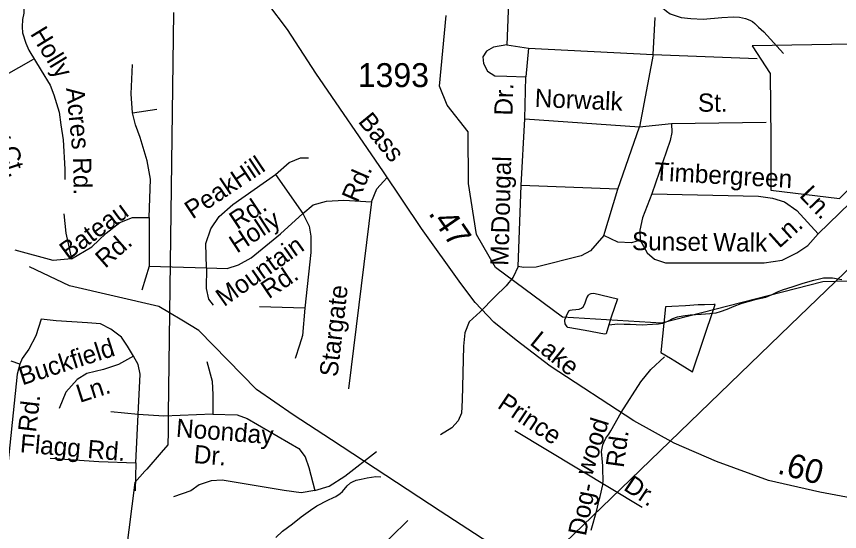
# Model space of a CAD drawing. Extents: x 2001466 to 2224147, y 644118 to 847247.
# Drawn here: x 2051357 to 2055654, y 689808 to 692499 of the extents above; entities that cross this region are included whole.
import ezdxf

# ---------------------------------------------------------------- set-up
doc = ezdxf.new("R2010")
doc.units = 0
for name, color, linetype in [('Exist Boundary Political City Limit New Hole', 7, 'Continuous'), ('Exist Hydrographic Creek Single Shore', 7, 'Continuous'), ('Exist Hydrographic Misc Water Feature', 7, 'Continuous'), ('Exist Road Non-System Type 51', 7, 'Continuous'), ('Exist Road Non-System Type 51 Label', 7, 'Continuous'), ('Exist Road Secondary Mileage Hundredths English Label', 7, 'Continuous'), ('Exist Road Secondary Type 51 Attributed', 7, 'Continuous'), ('Exist Road Secondary Type 51 Label', 7, 'Continuous'), ('Exist Road Secondary Type 51 Number Label', 7, 'Continuous'), ('Exist Utilities Electrical Transmission Line', 7, 'Continuous'), ('Map Preparation Boundary City Limit Buffer Line', 7, 'Continuous')]:
    doc.layers.add(name, color=color, linetype=linetype)

msp = doc.modelspace()

# ---------------------------------------------------------------- linework, layer by layer
at = {"layer": 'Exist Boundary Political City Limit New Hole'}
for points in [[(2055291, 692200.8), (2055294.9, 691856.9), (2055294.9, 691591.2), (2055654.6, 691548.2), (2056307.6, 692204.6), (2056307.6, 692259.4), (2055717.2, 692353.1), (2055197.1, 692345.3), (2055291, 692200.8)], [(2054794.5, 690699.9), (2054886.6, 690642.8), (2055000, 690978.4), (2055005.2, 690993.9), (2055000, 690993.8), (2054998.1, 690993.8), (2054949, 690992.5), (2054915.2, 690991.7), (2054849.2, 690987.6), (2054779, 690983.3), (2054744.5, 690981.7), (2054720.1, 690743.2), (2054771.5, 690713.6), (2054794.5, 690699.9)]]:
    msp.add_lwpolyline(points, dxfattribs=at)
at = {"layer": 'Exist Hydrographic Creek Single Shore'}
for p, q in [((2052219.8, 690911.5), (2052156.3, 690949.7)), ((2053568.5, 689915.2), (2053002, 690286.3)), ((2053822.9, 689748.5), (2053568.5, 689915.2))]:
    msp.add_line(p, q, dxfattribs=at)
for points in [[(2052156.3, 690949.7), (2052099.9, 690983.5), (2051634.1, 691091.4), (2051425.1, 691190.8)], [(2053002, 690286.3), (2052801, 690418.1), (2052609.1, 690550), (2052309.1, 690857.9), (2052219.8, 690911.5)]]:
    msp.add_lwpolyline(points, dxfattribs=at)
at = {"layer": 'Exist Hydrographic Misc Water Feature'}
for points in [[(2055633.4, 691114.4), (2055565.9, 691113.1), (2054725, 690897.3), (2054208.1, 690927.5), (2053858.1, 691187.3), (2053758, 691359.9), (2053716, 691626.5), (2053715.1, 691895.6), (2053606, 692035.6), (2053565, 692134.9), (2053600.5, 692503.7)], [(2054449.4, 690888.6), (2054495.6, 690892.5), (2054529.8, 690890.6), (2054561.6, 690890.6), (2054623.5, 690887), (2054677.2, 690891), (2054709.4, 690893), (2054731.4, 690897), (2054757.4, 690907.2), (2054783.5, 690921.1), (2054807.4, 690929.2), (2054835.1, 690935.2), (2054873.3, 690939.6), (2054931.3, 690943.3), (2054977, 690947.7), (2055009.2, 690949.8), (2055033.2, 690957.9), (2055067.5, 690969.7), (2055103.3, 690985.8), (2055140.9, 690999.9), (2055177, 691009.9), (2055221, 691021.9), (2055269, 691032), (2055302.9, 691046.3), (2055330.7, 691060.4), (2055357, 691070.2), (2055411.1, 691088.4), (2055458.9, 691104.3), (2055488.6, 691112.7), (2055519, 691120.7), (2055548.7, 691128.8), (2055570.7, 691132.7), (2055617, 691132.6), (2055666.6, 691125.1)], [(2057830.9, 689897.6), (2057633.9, 690060.5), (2057576.1, 690170), (2057426, 690333.8), (2057167, 690509.7), (2057033.1, 690650.2), (2056866, 690916), (2056774.9, 690999.9), (2056241, 691125.6), (2055633.4, 691114.4)], [(2054229.2, 690934.2), (2054241.3, 690960.3), (2054247.4, 690964.3), (2054257.5, 690966.4), (2054277.4, 690968.2), (2054295.2, 690970.4), (2054307.3, 690974.2), (2054315.5, 690982.3), (2054323.3, 690998.2), (2054335, 691028.4), (2054343.4, 691042.2), (2054349, 691048.2), (2054356.9, 691052.3), (2054371.1, 691052.6), (2054495.2, 691022.8), (2054461.3, 690928.6), (2054449.4, 690888.6)], [(2054449.4, 690888.6), (2054435.5, 690840.4), (2054427.5, 690838.4), (2054325.4, 690858.3), (2054235.4, 690874), (2054231.5, 690878.2), (2054221.4, 690892.3), (2054219.4, 690908.1), (2054219.6, 690914.1), (2054227.4, 690930), (2054229.2, 690934.2)], [(2052711.6, 689777.5), (2052745.9, 689809.6), (2052797.7, 689847.6), (2052843.5, 689885.7), (2052891.6, 689919.7), (2052925.7, 689941.8), (2052981.7, 689971.8), (2053011.6, 689986), (2053023.3, 689991.9), (2053047.3, 690006.1), (2053059.4, 690018), (2053083.2, 690046), (2053101.2, 690062.4), (2053111.1, 690068.2), (2053131.1, 690076.5), (2053157.2, 690082.3), (2053187.1, 690088.3), (2053233.1, 690096.3), (2053259.1, 690094.4)]]:
    msp.add_lwpolyline(points, dxfattribs=at)
at = {"layer": 'Exist Road Non-System Type 51'}
for points in [[(2054650.5, 693715.8), (2054676.9, 692673.7), (2054685.8, 692584.6), (2054706.6, 692557.9), (2054738.6, 692537.1), (2054750.3, 692526.9), (2054770.1, 692512.5), (2054785.9, 692506.2), (2054805.8, 692499.8), (2054827.7, 692493.3), (2054877.6, 692488.3), (2054941.5, 692485), (2055039.7, 692493), (2055099.7, 692495.8), (2055131.7, 692495.1), (2055163.6, 692488.5), (2055185.4, 692480), (2055199.2, 692471.8), (2055211, 692461.5), (2055230.6, 692443.1), (2055258.1, 692418.6), (2055361.8, 692304.4)], [(2053647, 692679.6), (2053911.4, 692667.7), (2053925.7, 692653.4), (2053928, 692617.7), (2053916.1, 692350.5)], [(2051397.4, 692612.1), (2051394.8, 692516.6), (2051387.9, 692482.2), (2051386.2, 692444.4), (2051387.9, 692413.5), (2051405.1, 692358.5), (2051420.4, 692323.1)], [(2054681.7, 692300.4), (2054691.2, 692493.5)], [(2053916.1, 692350.5), (2053847, 692338.6), (2053811.3, 692317.1), (2053792.3, 692288.5), (2053794.6, 692252.8), (2053816.1, 692212.2), (2053854.2, 692188.4), (2053916.1, 692186), (2054016.2, 692183.6)], [(2053916.1, 692350.5), (2054030.5, 692333.8)], [(2051420.4, 692323.1), (2051485.7, 692216.2), (2051533.2, 692139.6), (2051551, 692088.5), (2051579.5, 691998.7), (2051588.1, 691931.7), (2051600.1, 691854.7), (2051608.7, 691700.1), (2051608.7, 691646.9)], [(2054030.5, 692333.8), (2054016.2, 692183.6)], [(2054030.5, 692333.8), (2054681.7, 692300.4)], [(2054681.7, 692300.4), (2054610.2, 691921.5)], [(2054681.7, 692300.4), (2055223.8, 692279)], [(2055542, 691363.3), (2056491.9, 692284.2), (2056549, 692327.1)], [(2051163, 692169), (2051291.8, 692187.9), (2051446.3, 692275.5)], [(2051961.8, 691995.1), (2051955.5, 692095.2), (2051961.8, 692248.5)], [(2054011.4, 691963.9), (2054016.2, 692183.6)], [(2051961.8, 691995.1), (2052089.9, 692013.9)], [(2052049.3, 691447.8), (2052055.6, 691648), (2052039.9, 691744.9), (2052002.4, 691866.9), (2051977.4, 691932.6), (2051961.8, 691995.1)], [(2053992.3, 691615.9), (2054011.4, 691963.9)], [(2054011.4, 691963.9), (2054610.2, 691921.5)], [(2054496.3, 691596.8), (2054610.2, 691921.5)], [(2054610.2, 691921.5), (2054776, 691938.6)], [(2054776, 691938.6), (2054778.4, 691893.3), (2054768.8, 691850.4), (2054673.6, 691571.6)], [(2054776, 691938.6), (2055271.4, 691945.8)], [(2052708.8, 691673), (2052780.7, 691735.5), (2052840.1, 691760.5), (2052880.7, 691760.5)], [(2052349.4, 691185.1), (2052346.2, 691313.3), (2052371.3, 691388.4), (2052415, 691454), (2052486.9, 691516.6), (2052708.8, 691673)], [(2052708.8, 691673), (2052852.6, 691469.7)], [(2053209.5, 691530), (2053237.7, 691598.8), (2053272.1, 691636.4), (2053292.9, 691657.2)], [(2053975.7, 691191.7), (2053992.3, 691615.9)], [(2054496.3, 691596.8), (2053992.3, 691615.9)], [(2054422.5, 691353.7), (2054496.3, 691596.8)], [(2054673.6, 691571.6), (2054625, 691446.7), (2054610.7, 691382.3), (2054613.1, 691329.9)], [(2054673.6, 691571.6), (2055230.9, 691559.7), (2055304.8, 691550.1), (2055366.7, 691531.1), (2055431, 691485.8), (2055542, 691363.3)], [(2052852.6, 691469.7), (2052906.4, 691514.4), (2052975.1, 691533.2), (2053065.8, 691539.4), (2053209.5, 691530)], [(2053209.5, 691530), (2053090.8, 690552.9)], [(2051603.6, 691468), (2051614.8, 691367.1), (2051644.8, 691232.6), (2051548.6, 691224), (2051350.7, 691278)], [(2051644.8, 691232.6), (2051749.3, 691294.5), (2051824.3, 691366.5), (2051896.2, 691422.8), (2051961.8, 691447.8), (2052049.3, 691447.8)], [(2052049.3, 691447.8), (2052049.3, 691194.4)], [(2052349.4, 691185.1), (2052456.3, 691181.6), (2052515.7, 691200.4), (2052581.3, 691237.9), (2052734.4, 691363), (2052852.6, 691469.7)], [(2052852.6, 691469.7), (2052884.5, 691403.7), (2052893.9, 691350.5), (2052893.9, 691266.1), (2052862.6, 690975.2)], [(2054613.1, 691329.9), (2054650.2, 691264.1), (2054688.3, 691230.8), (2054745.5, 691211.7), (2055260, 691211.7), (2055355.2, 691226), (2055431.5, 691264.1), (2055488.6, 691302.3), (2055542, 691363.3)], [(2054422.5, 691353.7), (2054354.4, 691275.1), (2054304.4, 691248.9), (2054070.9, 691189.3), (2054004.3, 691186.9), (2053975.7, 691191.7)], [(2054613.1, 691329.9), (2054567.8, 691315.6), (2054496.3, 691320.4), (2054422.5, 691353.7)], [(2052049.3, 691194.4), (2052011.8, 691069.3)], [(2052049.3, 691194.4), (2052349.4, 691185.1)], [(2052349.4, 691185.1), (2052346.9, 691078.4), (2052359.4, 691022.1), (2052384.4, 690990.8)], [(2053975.7, 691191.7), (2053949.5, 691136.6), (2053913.7, 691091.3), (2053854.2, 691034.1), (2053778, 690955.5)], [(2052862.6, 690975.2), (2052625.1, 690981.4)], [(2052862.6, 690975.2), (2052850.1, 690831.3), (2052834.5, 690781.3), (2052812.6, 690712.5)], [(2053778, 690955.5), (2053719.9, 690902.8), (2053698.4, 690845.6), (2053691.3, 690776.5), (2053684.1, 690495.2), (2053679.4, 690426.1), (2053662.7, 690385.6), (2053629.3, 690349.8), (2053569.8, 690314.1)], [(2051486.1, 690917.6), (2051457.9, 690830.1), (2051420.4, 690761.3), (2051386.1, 690711.2), (2051373.6, 690683.1)], [(2051967.4, 690723.7), (2051936.2, 690776.9), (2051904.9, 690823.8), (2051848.6, 690864.5), (2051795.5, 690892.6), (2051726.7, 690898.9), (2051564.2, 690908.3), (2051486.1, 690917.6)], [(2051967.4, 690723.7), (2051889.3, 690679.9), (2051811.1, 690654.9), (2051723.6, 690633), (2051673.6, 690601.7), (2051614.2, 690536.1), (2051579.8, 690451.6)], [(2051992.4, 690420.3), (2052001.8, 690629.9), (2051992.4, 690679.9), (2051967.4, 690723.7)], [(2054514.1, 690429.7), (2054616.9, 690589.4), (2054669.3, 690653.7), (2054740.7, 690720.5)], [(2051373.6, 690683.1), (2051361.1, 690629.9), (2051301.7, 690057.5)], [(2051373.6, 690683.1), (2051329.8, 690698.7)], [(2052350, 690696.8), (2052378.1, 690593.6), (2052381.3, 690521.7), (2052381.3, 690421.6)], [(2051992.4, 690420.3), (2051848.6, 690432.8)], [(2051979.9, 690167), (2051992.4, 690420.3)], [(2052381.3, 690421.6), (2052126.8, 690411), (2051992.4, 690420.3)], [(2052381.3, 690421.6), (2052508.2, 690417.2), (2052561.3, 690398.4), (2052830.1, 690242.1), (2052864.5, 690198.3), (2052883.2, 690142), (2052914.5, 690023.1)], [(2054356.9, 689815), (2054386.6, 689920.3), (2054397.6, 689966), (2054404.1, 689991.9), (2054417.3, 690051.6), (2054419.9, 690077.6), (2054418.9, 690129.6), (2054417.4, 690151.6), (2054415.7, 690169.7), (2054410.9, 690225.8), (2054417.6, 690261.6), (2054423.9, 690273.5), (2054434.3, 690295.3), (2054448.8, 690317), (2054459.1, 690334.8), (2054514.1, 690429.7)], [(2053959.5, 690336.7), (2054624, 689936.3)], [(2052914.5, 690023.1), (2052989.5, 690045), (2053070.8, 690098.2), (2053236.4, 690226.4)], [(2051533, 690192), (2051786.1, 690173.2), (2051979.9, 690167)], [(2051979.9, 690167), (2051976.8, 690020)], [(2052914.5, 690023.1), (2052842.6, 690010.6), (2052755.1, 690023.1), (2052430, 690076.3), (2052373.8, 690073.2), (2052311.2, 690051.3), (2052267.5, 690020), (2052176.8, 689988.7)], [(2053222.4, 689692.3), (2053399.6, 689865.3)]]:
    msp.add_lwpolyline(points, dxfattribs=at)
at = {"layer": 'Exist Road Secondary Type 51 Attributed'}
msp.add_lwpolyline([(2057671.9, 689435.8), (2057551.9, 689500.6), (2057342.1, 689604.8), (2057192.2, 689663.2), (2056983.9, 689724), (2056542.1, 689823.5), (2055933, 689942.7), (2055551.2, 690013.7), (2055282.9, 690075.3), (2055011.5, 690174), (2054790.6, 690270.3), (2054579.2, 690387.2), (2054143.7, 690672.2), (2053965.4, 690808), (2053848.6, 690901.1), (2053750.8, 691005.3), (2053676.6, 691103.2), (2053471.5, 691391.4), (2053272.7, 691686.7), (2052919.2, 692202.2), (2052770.9, 692431.2), (2052668.3, 692566.2)], dxfattribs=at)
at = {"layer": 'Exist Utilities Electrical Transmission Line'}
for p, q in [((2052176.5, 692518.6), (2052156.3, 690949.7)), ((2055396.8, 690886), (2055633.4, 691114.4)), ((2052156.3, 690949.7), (2052149.4, 690419.2)), ((2054768.2, 690279.2), (2055396.8, 690886)), ((2052149.4, 690419.2), (2052148.3, 690329.2)), ((2054461.1, 689982.7), (2054768.2, 690279.2)), ((2054312.9, 689839.6), (2054461.1, 689982.7)), ((2054058.5, 689594.1), (2054312.9, 689839.6))]:
    msp.add_line(p, q, dxfattribs=at)
for points in [[(2055633.4, 691114.4), (2056033.6, 691500.7), (2057399.4, 692809)], [(2052148.3, 690329.2), (2052147.4, 690260.3), (2052113, 690220.7)], [(2052113, 690220.7), (2052037.6, 690134.1), (2052027.5, 690123)], [(2052027.5, 690123), (2051973.8, 690064), (2051927.6, 689693.9)]]:
    msp.add_lwpolyline(points, dxfattribs=at)
at = {"layer": 'Map Preparation Boundary City Limit Buffer Line'}
for points in [[(2055291, 692200.8), (2055294.9, 691856.9), (2055294.9, 691591.2), (2055654.6, 691548.2), (2056307.6, 692204.6), (2056307.6, 692259.4), (2055717.2, 692353.1), (2055197.1, 692345.3), (2055291, 692200.8)], [(2054794.5, 690699.9), (2054886.6, 690642.8), (2055000, 690978.4), (2055005.2, 690993.9), (2055000, 690993.8), (2054998.1, 690993.8), (2054949, 690992.5), (2054915.2, 690991.7), (2054849.2, 690987.6), (2054779, 690983.3), (2054744.5, 690981.7), (2054720.1, 690743.2), (2054771.5, 690713.6), (2054794.5, 690699.9)]]:
    msp.add_lwpolyline(points, dxfattribs=at)

# ---------------------------------------------------------------- texts
at = {"layer": 'Exist Road Non-System Type 51 Label'}
for s, rotation, p in [('Holly', 301.418, (2051426, 692408.3)), ('Holiday Ct.', 287.9206, (2051129.2, 692241.4)), ('Dr.', 88.4479, (2053946, 691980)), ('Acres', 275.6158, (2051615.5, 692123.9)), ('Norwalk', 357.5094, (2054061.2, 692026.5)), ('St.', 359.744, (2054914.2, 692001.2)), ('Rd.', 270.798, (2051652.4, 691762.6)), ('PeakHill', 33.7235, (2052275.6, 691437.7)), ('McDougal', 88.4478, (2053924.8, 691195.4)), ('Rd.', 66.6986, (2053138.3, 691521.5)), ('Timbergreen', 356.816, (2054685, 691642.3)), ('Ln.', 313.5435, (2055440.1, 691560)), ('Rd.', 33.7235, (2052508.7, 691382.7)), ('Bateau', 36.3151, (2051626, 691223.5)), ('Holly', 33.2103, (2052507.5, 691259.2)), ('Ln.', 41.9273, (2055338.7, 691284.3)), ('Rd.', 41.2682, (2051820, 691179.8)), ('Sunset', 359.2879, (2054569.9, 691278.3)), ('Walk', 359.2879, (2054993.5, 691273.1)), ('Mountain', 35.329, (2052440.5, 690979.6)), ('Rd.', 33.954, (2052673.7, 691020.7)), ('Stargate', 83.4225, (2053032.4, 690612.9)), ('Buckfield', 17.7656, (2051386.9, 690571.3)), ('Ln.', 17.7656, (2051687.1, 690479.9)), ('Rd.', 83.2986, (2051458.4, 690323.5)), ('Prince', 326.0702, (2053862.1, 690457.9)), ('Noonday', 355.4801, (2052187.5, 690303.4)), ('wood', 72.7176, (2054361.3, 690093)), ('Rd.', 82.1916, (2054526.7, 690138.4)), ('Flagg Rd.', 355.2, (2051372.5, 690222.3)), ('Dr.', 355.4801, (2052279.7, 690166.3)), ('Dr.', 326.0702, (2054521, 690029.2)), ('Dog-', 78.5776, (2054329, 689781.2))]:
    msp.add_text(s, height=95, rotation=rotation, dxfattribs=at).set_placement(p)
at = {"layer": 'Exist Road Secondary Mileage Hundredths English Label'}
for s, rotation, p in [('.47', 304.5232, (2053504, 691470.5)), ('.60', 344.701, (2055324.7, 690112.8))]:
    msp.add_text(s, height=125, rotation=rotation, dxfattribs=at).set_placement(p)
at = {"layer": 'Exist Road Secondary Type 51 Label'}
for s, rotation, p in [('Bass', 309.273, (2053136.8, 691948.3)), ('Lake', 321.0265, (2054031.6, 690788.6))]:
    msp.add_text(s, height=95, rotation=rotation, dxfattribs=at).set_placement(p)
at = {"layer": 'Exist Road Secondary Type 51 Number Label'}
msp.add_text('1393', height=125, dxfattribs=at).set_placement((2053138.6, 692129.6))

doc.saveas('drawing.dxf')
